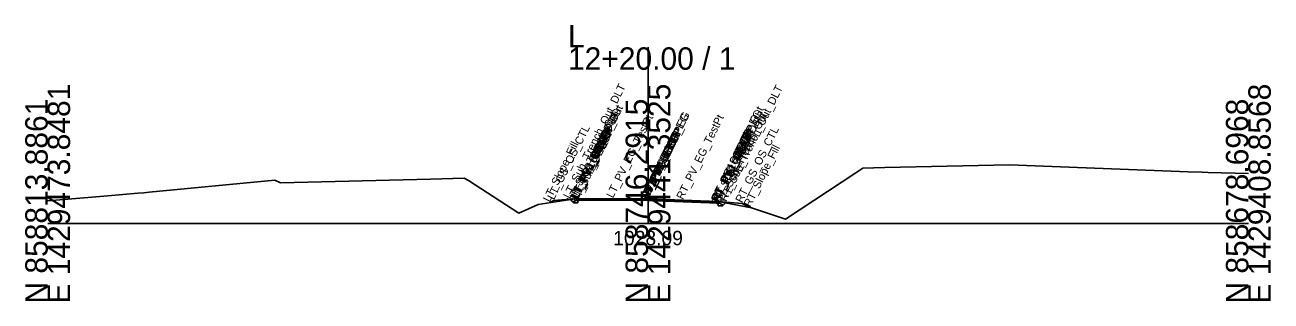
# Model space of a CAD drawing. Extents: x -26 to 2303, y -10 to 19558.
# Drawn here: x 1147.2 to 1302.8, y -9.7 to 24.8 of the extents above; entities that cross this region are included whole.
import ezdxf

# ---------------------------------------------------------------- set-up
doc = ezdxf.new("R2010")
doc.units = 0
for name, color, linetype in [('Default', 7, 'Continuous'), ('Exist CMT Pavement', 7, 'Continuous'), ('Exist Cross Section Cell', 7, 'Continuous'), ('Exist XS Center Line Elevation Label', 7, 'Continuous'), ('Exist XS Ground Line', 7, 'Continuous'), ('Prop CMT Pvmt Course 1', 7, 'Continuous'), ('Prop CMT Pvmt Course 1 Wedge', 7, 'Continuous'), ('Prop CMT Pvmt Course 2', 7, 'Continuous'), ('Prop CMT Pvmt Course 2 Wedge', 7, 'Continuous'), ('Prop CMT Pvmt Surface', 7, 'Continuous'), ('Prop CMT Pvmt Surface Shoulder', 7, 'Continuous'), ('Prop CMT Pvmt Wedge Surface 1', 7, 'Continuous'), ('Prop CMT Pvmt Wedge Surface 2', 7, 'Continuous'), ('Prop CMT Shld Paved Course 1', 7, 'Continuous'), ('Prop CMT Shld Paved Course 2', 7, 'Continuous'), ('Prop CMT Slope Grass', 7, 'Continuous'), ('Prop CMT Subgrade Earthwork', 7, 'Continuous'), ('Prop XS Dump Level', 7, 'Continuous')]:
    doc.layers.add(name, color=color, linetype=linetype)

msp = doc.modelspace()

# ---------------------------------------------------------------- linework, layer by layer
at = {"layer": 'Exist CMT Pavement'}
for points in [[(1225, 3.09), (1216.25, 3.12)], [(1216.25, 3.12), (1220.62, 3.11)], [(1220.62, 3.11), (1225, 3.09)], [(1229.37, 2.92), (1225, 3.09)], [(1225, 3.09), (1233.75, 2.74)], [(1233.75, 2.74), (1229.37, 2.92)]]:
    msp.add_lwpolyline(points, dxfattribs=at)
at = {"layer": 'Exist Cross Section Cell'}
for p, q in [((1225, 0), (1225, 22.03)), ((1150, 0), (1225, 0)), ((1225, 0), (1300, 0))]:
    msp.add_line(p, q, dxfattribs=at)
at = {"layer": 'Exist XS Ground Line'}
msp.add_lwpolyline([(1150, 2.83), (1157.5, 3.48), (1161.26, 3.79), (1162.02, 3.85), (1162.7, 3.92), (1178.4, 5.43), (1179.08, 5.08), (1197.83, 5.56), (1202.04, 5.67), (1202.59, 5.37), (1208.88, 1.31), (1211.27, 2.4), (1212.91, 2.65), (1216.14, 3.12), (1219.2, 3.11), (1225.12, 3.09), (1228.21, 2.97), (1233.78, 2.74), (1237.94, 1.96), (1242.18, 0.54), (1250.96, 6.34), (1251.85, 6.92), (1254.6, 6.99), (1270.17, 7.34), (1292.5, 6.48), (1294.24, 6.41), (1294.99, 6.38), (1300, 6.25)], dxfattribs=at)
at = {"layer": 'Prop CMT Pvmt Course 1'}
for points in [[(1225, 3.1), (1216.25, 3.13)], [(1216.25, 3.13), (1216.25, 2.92), (1216.25, 2.92), (1216.25, 3)], [(1216.25, 3), (1225, 2.97)], [(1225, 2.89), (1225, 3.1)], [(1225, 3.1), (1233.75, 2.75)], [(1225, 2.89), (1225, 3.1)], [(1225, 2.97), (1225, 2.89), (1225, 2.89)], [(1233.75, 2.62), (1225, 2.97)], [(1225, 2.97), (1225, 2.89), (1225, 2.89)], [(1233.75, 2.75), (1233.75, 2.54), (1233.75, 2.54), (1233.75, 2.62)]]:
    msp.add_lwpolyline(points, dxfattribs=at)
at = {"layer": 'Prop CMT Pvmt Course 1 Wedge'}
for points in [[(1225, 2.97), (1216.25, 3)], [(1225, 2.97), (1233.75, 2.62)]]:
    msp.add_lwpolyline(points, dxfattribs=at)
at = {"layer": 'Prop CMT Pvmt Course 2'}
for points in [[(1216.25, 2.58), (1216.25, 2.58), (1216.25, 2.92), (1216.25, 2.92)], [(1216.25, 2.92), (1216.25, 2.58)], [(1233.75, 2.21), (1233.75, 2.21), (1233.75, 2.54), (1233.75, 2.54)], [(1233.75, 2.54), (1233.75, 2.21)]]:
    msp.add_lwpolyline(points, dxfattribs=at)
at = {"layer": 'Prop CMT Pvmt Course 2 Wedge'}
for points in [[(1225, 2.89), (1216.25, 2.92)], [(1225, 2.89), (1233.75, 2.54)]]:
    msp.add_lwpolyline(points, dxfattribs=at)
at = {"layer": 'Prop CMT Pvmt Surface'}
for points in [[(1225, 3.1), (1216.25, 3.13)], [(1225, 3.1), (1233.75, 2.75)]]:
    msp.add_lwpolyline(points, dxfattribs=at)
at = {"layer": 'Prop CMT Pvmt Surface Shoulder'}
for points in [[(1216.25, 3.13), (1216.25, 3.13)], [(1233.75, 2.75), (1233.75, 2.75)]]:
    msp.add_lwpolyline(points, dxfattribs=at)
at = {"layer": 'Prop CMT Pvmt Wedge Surface 1'}
for points in [[(1216.25, 2.92), (1216.25, 3.13)], [(1225, 2.97), (1216.25, 3)], [(1216.25, 3), (1216.25, 2.92), (1216.25, 2.92)], [(1225, 2.97), (1233.75, 2.62)], [(1233.75, 2.54), (1233.75, 2.75)], [(1233.75, 2.62), (1233.75, 2.54), (1233.75, 2.54)]]:
    msp.add_lwpolyline(points, dxfattribs=at)
at = {"layer": 'Prop CMT Pvmt Wedge Surface 2'}
for points in [[(1216.25, 2.92), (1216.25, 3.13)], [(1225, 2.89), (1216.25, 2.92)], [(1225, 2.89), (1233.75, 2.54)], [(1233.75, 2.54), (1233.75, 2.75)]]:
    msp.add_lwpolyline(points, dxfattribs=at)
at = {"layer": 'Prop CMT Shld Paved Course 1'}
for points in [[(1216.25, 3.13), (1216.04, 2.91)], [(1216.25, 3.13), (1216.25, 3.13)], [(1216.25, 2.92), (1216.25, 3.13)], [(1216.04, 2.91), (1216.25, 2.92)], [(1233.75, 2.75), (1233.75, 2.75)], [(1233.75, 2.75), (1233.96, 2.54)], [(1233.75, 2.54), (1233.75, 2.75)], [(1233.96, 2.54), (1233.75, 2.54)]]:
    msp.add_lwpolyline(points, dxfattribs=at)
at = {"layer": 'Prop CMT Shld Paved Course 2'}
for points in [[(1216.04, 2.91), (1215.7, 2.57)], [(1215.7, 2.57), (1216.25, 2.58)], [(1216.25, 2.92), (1216.04, 2.91)], [(1216.04, 2.91), (1216.04, 2.91)], [(1216.25, 2.58), (1216.25, 2.92)], [(1233.75, 2.54), (1233.96, 2.54)], [(1233.75, 2.21), (1233.75, 2.54)], [(1234.3, 2.2), (1233.75, 2.21)], [(1233.96, 2.54), (1233.96, 2.54)], [(1233.96, 2.54), (1234.3, 2.2)]]:
    msp.add_lwpolyline(points, dxfattribs=at)
at = {"layer": 'Prop CMT Slope Grass'}
for points in [[(1216.25, 3.13), (1213.25, 2.89), (1212.72, 2.62)], [(1233.75, 2.75), (1236.75, 2.51), (1237.78, 1.99)]]:
    msp.add_lwpolyline(points, dxfattribs=at)
at = {"layer": 'Prop CMT Subgrade Earthwork'}
for points in [[(1216.25, 2.58), (1216.26, 3.12)], [(1215.7, 2.57), (1215.23, 3.04)], [(1216.25, 2.58), (1215.7, 2.57)], [(1216.25, 2.58), (1216.25, 2.58)], [(1233.75, 2.21), (1233.73, 2.74)], [(1233.75, 2.21), (1233.75, 2.21)], [(1233.75, 2.21), (1234.3, 2.2)], [(1234.3, 2.2), (1234.77, 2.67)]]:
    msp.add_lwpolyline(points, dxfattribs=at)

# ---------------------------------------------------------------- texts
at = {"layer": 'Default'}
msp.add_text('-', height=0.0001, dxfattribs=at).set_placement((1150, 0))
at = {"layer": 'Exist Cross Section Cell'}
for s, p in [('L', (1215, 22.03)), ('12+20.00 / 1', (1215, 19.23))]:
    msp.add_text(s, height=2.8, dxfattribs=at).set_placement(p)
for s, p in [('E 1429473.8481', (1152.8, -10)), ('E 1429441.3525', (1227.8, -10)), ('E 1429408.8568', (1302.8, -10)), ('N 858813.8861', (1150, -10)), ('N 858746.2915', (1225, -10)), ('N 858678.6968', (1300, -10))]:
    msp.add_text(s, height=2.8, rotation=90, dxfattribs=at).set_placement(p)
at = {"layer": 'Exist XS Center Line Elevation Label'}
msp.add_text('1028.09', height=1.8, dxfattribs=at).set_placement((1220.66, -2.71))
at = {"layer": 'Prop XS Dump Level'}
for s, p in [('LT_Sub_Trench_Out_DLT', (1215.23, 3.04)), ('RT_Sub_Trench_Out_DLT', (1234.77, 2.67)), ('LT_Sub_Trench_Out', (1215.7, 2.57)), ('LT_PV_OEEOP_EG', (1216.25, 3.12)), ('LT_PV_Sub_Tie_Out', (1216.26, 3.12)), ('RT_PV_Sub_Tie_Out', (1233.73, 2.74)), ('RT_PV_OEEOP_EG', (1233.75, 2.74)), ('LT_PS2_Shelf_Out', (1216.04, 2.91)), ('LT_PV1_OEEOP', (1216.25, 3)), ('LT_PV2_OEEOP', (1216.25, 2.92)), ('LT_PV_EG_TestPt', (1220.62, 3.11)), ('RT_PV_IEEOP_EG', (1225, 3.09)), ('LT_PV_IEEOP_EG', (1225, 3.09)), ('RT_PV_EG_TestPt', (1229.37, 2.92)), ('RT_PS2_Shelf_Out', (1233.96, 2.54)), ('RT_Sub_Trench_Out', (1234.3, 2.2)), ('LT_GS_OS_CTL', (1213.25, 2.89)), ('LT_PS2_OEOP', (1216.04, 2.91)), ('LT_Sub_OEEOP', (1216.25, 2.58)), ('LT_PV1_OEOT', (1216.25, 3.13)), ('LT_PS1_OEOP', (1216.25, 3.13)), ('LT_PV2_OEOT', (1216.25, 2.92)), ('LT_Sub_OEOT', (1216.25, 2.58)), ('RT_PV1_IEEOP', (1225, 2.97)), ('RT_PV2_IEEOP', (1225, 2.89)), ('LT_PV1_IEEOP', (1225, 2.97)), ('LT_PV2_IEEOP', (1225, 2.89)), ('RT_PV1_OEEOP', (1233.75, 2.62)), ('RT_PV2_OEEOP', (1233.75, 2.54)), ('RT_Sub_OEEOP', (1233.75, 2.21)), ('RT_PV1_OEOT', (1233.75, 2.75)), ('RT_PS1_OEOP', (1233.75, 2.75)), ('RT_PV2_OEOT', (1233.75, 2.54)), ('RT_Sub_OEOT', (1233.75, 2.21)), ('RT_PS2_OEOP', (1233.96, 2.54)), ('RT_GS_OS_CTL', (1236.75, 2.51)), ('LT_Slope_Fill', (1212.72, 2.62)), ('RT_Slope_Fill', (1237.78, 1.99)), ('PV1_PGL', (1225, 3.1)), ('PV2_PGL', (1225, 2.89))]:
    msp.add_text(s, height=1, rotation=63.5833, dxfattribs=at).set_placement(p)

doc.saveas('drawing.dxf')
